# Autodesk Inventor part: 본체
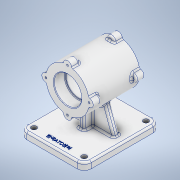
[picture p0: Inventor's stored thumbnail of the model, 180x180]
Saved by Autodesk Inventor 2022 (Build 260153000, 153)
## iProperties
Created: 2023-05
Part Number: 본체
Material: 알루미늄 6061
Document SubType Name: Modeling
Designer: Admin
Mass: 1223.64 g
Surface Area: 788.435 cm^2
Volume: 453.199 cm^3
Density: 2.7 g/cm^3
Appearance: 알루미늄 - 평지
Author: Admin
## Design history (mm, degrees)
sketch "스케치1"
  geometry: L1 (55, 70)-(-55, 70); L2 (-55, 70)-(-55, -60); L3 (-55, -60)-(55, -60); L4 (55, -60)-(55, 70); L5 (0, -86)-(0, 96) reference; L6 (77, 0)-(-77, 0) reference
  constraints: 8 end point, 2 parallel, 1 horizontal, 1 perpendicular, 1 other
  dimensions: "d63" = 130 distance of L3.end L1.start; "d64" = 110 distance of L2.end L3.end; "d65" = 70 distance between parallel lines of L1 L6
extrude "돌출1" new body sketch "스케치1" distance "d2" = 12; taper "d3" = 0 deg
sketch "스케치11"
  geometry: L1 (0, -2.4)-(0, 14.4) reference; L2 (-77, 0)-(77, 0) reference; C1 r 37 at (0, 82); 1 further point
  constraints: 1 centre point, 1 point on line
  dimensions: "d66" = 74 diameter of C1; "d67" = 82 distance from line of L2 C1.centre
extrude "돌출7" join sketch "스케치11" stored distance "d68" = 87; taper "d69" = 0 deg
sketch "스케치12"
  geometry: L1 (5, 20)-(-5, 20); L2 (-5, 20)-(-5, -20); L3 (-5, -20)-(5, -20); L4 (5, -20)-(5, 20); L5 (-77, 0)-(77, 0) reference; L6 (0, -86)-(0, 96) reference; 1 further point
  constraints: 8 end point, 2 parallel, 1 horizontal, 1 perpendicular, 2 other
  dimensions: "d70" = 40 distance of L3.end L1.start; "d71" = 10 distance of L2.end L3.end
extrude "돌출8" join sketch "스케치12" stored distance "d72" = 10; taper "d73" = 0 deg
sketch "스케치13"
  geometry: L1 (55, 12)-(-55, 12) reference; L2 (-41, 12)-(-20.247, 69.019); L3 (-55, 0)-(-55, 12) reference; 1 further point
  constraints: 2 end point, 1 point on line
  dimensions: "d74" = 14 distance from line of L3 L2.start; "d75" = 110 deg angle of L1 L2
feature "리브2" sketch "스케치13" dims "d76" = 1, "d77" = 10, "d78" = 0, "d79" = 0, "d80" = 1, "d81" = 1
sketch "스케치14"
  geometry: L1 (0, -105.8)-(0, 60.8) reference; C1 r 37 at (0, 0) reference; C2 r 7 at (0, 37); 2 further points
  constraints: 1 centre point, 1 point on line, 1 vertical alignment, 1 other
  dimensions: "d82" = 14 diameter of C2
extrude "돌출9" join sketch "스케치14" distance "d83" = 14; taper "d84" = 0 deg
sketch "스케치15"
  geometry: A1 r 7 centre (0, 119) between (6.969, 118.338) and (-6.969, 118.338) reference; 2 further points
  constraints: 1 coincident
hole "구멍2" sketch "스케치15" at (0, 119) diameter "d85" = 3.242; stored, may be unused: countersink angle "d89" = 90 deg, drill point angle "d91" = 118 deg; dims "d86" = 8, "d87" = 4, "d88" = 2, "d90" = 10
fillet "모깎기5" dims "d95" = 12
sketch "스케치16"
  geometry: L1 (82, 66.7)-(82, -66.473); L2 (0, -48)-(0, 58) reference; L3 (89, 43.5)-(75, 43.5) reference; L4 (82, 43.5)-(105.5, 43.5); L5 (105.5, 43.5)-(105.5, 24.5); L6 (105.5, 24.5)-(82, 24.5); L7 (82, 24.5)-(82, 43.5); L8 (82, 24.5)-(103, 24.5); L9 (103, 24.5)-(103, -24.5); L10 (103, -24.5)-(82, -24.5); L11 (82, -24.5)-(82, 24.5); L12 (88.969, -43.5)-(118.338, -43.5) reference; L13 (82, -24.5)-(105.5, -24.5); L14 (105.5, -24.5)-(105.5, -43.5); L15 (105.5, -43.5)-(82, -43.5); L16 (82, -43.5)-(82, -24.5); 7 further points
  constraints: 26 end point, 6 parallel, 3 horizontal, 3 perpendicular, 1 midpoint, 1 point on line, 1 vertical
  dimensions: "d96" = 82 distance between parallel lines of L2 L1; "d97" = 47 diameter of L5 L1; "d98" = 42 diameter of L9 L1; "d99" = 47 diameter of L14 L1; "d100" = 19 distance of L4.end L5.end; "d101" = 19 distance of L13.end L14.end
revolve "회전2" sketch "스케치16" stored, may be unused: angle "d102" = 90 deg
sketch "스케치17"
  geometry: L1 (0, 86)-(0, -96) reference; 2 further points
  constraints: 1 point on line, 1 other
  dimensions: "d103" = 58 distance of point (0, 0) point (0, -58)
feature "엠보싱2" sketch "스케치17" dims "d104" = 0.5, "d105" = 0
fillet "모깎기6" dims "d106" = 3
fillet "모깎기7" dims "d107" = 3
fillet "모깎기8" dims "d108" = 3
chamfer "모따기2" distance "d109" = 1; stored, may be unused: second distance "d110" = 2, angle "d111" = 45 deg
fillet "모깎기9" dims "d112" = 1
sketch "스케치18"
  geometry: C1 r 4.5 at (-43, -58); A1 r 12 centre (-43, -58) between (-55, -58) and (-43, -70) reference; 1 further point
  constraints: 1 centre point, 1 coincident
  dimensions: "d113" = 9 diameter of C1
extrude "돌출10" cut sketch "스케치18" extent not by distance; stored distance "d114" = 0; taper "d115" = 0 deg
sketch "스케치19"
  geometry: C1 r 4.5 at (-43, 48); A1 r 12 centre (-43, 48) between (-43, 60) and (-55, 48) reference; 1 further point
  constraints: 1 centre point, 1 coincident
  dimensions: "d116" = 9 diameter of C1
extrude "돌출11" cut sketch "스케치19" extent not by distance; stored distance "d117" = 0; taper "d118" = 0 deg
node "솔리드1"
mirror "미러8"
pattern_circular "원형 패턴3" dims angle "d93" = 360 deg
mirror "미러9"
mirror "미러10"
mirror "미러11"
feature "A9D066F2-1C7D-4E18-AEED-F7BC21143FA4" dims "d85" = 3.242, "d86" = 8, "d87" = 4, "d88" = 2, "d89" = 90 deg, "d90" = 10, "d91" = 118 deg
